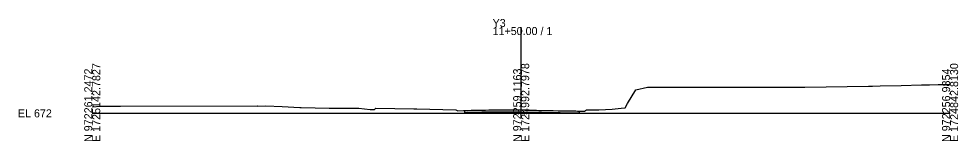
# Model space of a CAD drawing. Extents: x -26 to 303, y -10 to 3017.
# Drawn here: x -25.7 to 302.8, y 1490.3 to 1532.9 of the extents above; entities that cross this region are included whole.
import ezdxf

# ---------------------------------------------------------------- set-up
doc = ezdxf.new("R2010")
doc.units = 0
for name, color, linetype in [('Default', 7, 'Continuous'), ('Exist Other Culture Gate Leader', 7, 'Continuous'), ('Exist Roads Soil Text', 7, 'Continuous'), ('Exist Structure Minor Culvert Topo Terminator', 7, 'Continuous')]:
    doc.layers.add(name, color=color, linetype=linetype)

msp = doc.modelspace()

# ---------------------------------------------------------------- linework, layer by layer
at = {"layer": 'Exist Other Culture Gate Leader'}
for p, q in [((130.21, 1500.97), (130.21, 1500.3)), ((170.27, 1500.79), (170.27, 1500.12))]:
    msp.add_line(p, q, dxfattribs=at)
for points in [[(0, 1502.3), (2.84, 1502.51), (9.84, 1502.55), (57.83, 1502.66), (57.95, 1502.52), (60.76, 1502.64), (66.45, 1502.39), (72.54, 1502.08), (73.07, 1502.06), (82.84, 1501.83), (92.19, 1501.82), (93.19, 1501.81), (97.24, 1501.38), (97.81, 1501.36), (98.72, 1501.35), (99.14, 1501.85), (112.42, 1501.58), (112.85, 1501.57), (113.53, 1501.55), (127.17, 1501.27), (127.88, 1500.83), (129.8, 1500.94), (130.21, 1500.97), (131.22, 1501.04), (132.51, 1501.08), (133.72, 1501.11), (135.04, 1501.13), (136.22, 1501.14), (137.57, 1501.16), (138.7, 1501.17), (139.13, 1501.18), (139.68, 1501.19), (141.19, 1501.2), (142.28, 1501.21), (143.69, 1501.22), (145.15, 1501.22), (146.19, 1501.22), (147.2, 1501.21), (148.7, 1501.2), (149.42, 1501.19), (150, 1501.17), (151.23, 1501.13), (152.18, 1501.12), (153.73, 1501.1), (155.34, 1501.06), (156.23, 1501.04), (157.1, 1501.02), (158.73, 1500.98), (159.36, 1500.97), (159.88, 1500.96), (160.51, 1500.95), (161.21, 1500.94), (162.91, 1500.92), (163.7, 1500.91), (164.46, 1500.9), (166.19, 1500.87), (166.93, 1500.86), (168.69, 1500.83), (169.14, 1500.82), (169.72, 1500.81), (170.27, 1500.79), (171.8, 1500.74), (172.13, 1500.73), (172.85, 1501.2), (175.21, 1501.19), (177.16, 1501.2), (181.77, 1501.49), (184.98, 1501.75), (186.31, 1501.88), (187.21, 1503.39), (190.07, 1508.16), (194.2, 1509.13), (214.63, 1509.16), (222.7, 1509.11), (249.24, 1509.07), (271.43, 1509.46), (272.85, 1509.44), (275.5, 1509.57), (282.85, 1509.75), (290, 1509.91), (292.85, 1509.93), (295.79, 1510.01), (298.81, 1510.02), (300, 1510.03)], [(130.21, 1500.3), (131.25, 1500.38), (132.52, 1500.41), (133.73, 1500.44), (135.05, 1500.46), (136.23, 1500.48), (137.58, 1500.49), (138.71, 1500.5), (139.14, 1500.51), (139.69, 1500.52), (141.2, 1500.54), (142.28, 1500.55), (143.69, 1500.56), (145.15, 1500.55), (146.19, 1500.55), (147.19, 1500.54), (148.69, 1500.54), (149.4, 1500.52), (149.98, 1500.5), (151.22, 1500.46), (152.17, 1500.45), (153.72, 1500.43), (155.32, 1500.39), (156.22, 1500.37), (157.08, 1500.35), (158.71, 1500.31), (159.35, 1500.3), (159.87, 1500.29), (160.5, 1500.28), (161.2, 1500.28), (162.91, 1500.26), (163.69, 1500.25), (164.44, 1500.23), (166.18, 1500.2), (166.92, 1500.19), (168.68, 1500.16), (169.13, 1500.15), (169.7, 1500.14), (170.27, 1500.12)]]:
    msp.add_lwpolyline(points, dxfattribs=at)
at = {"layer": 'Exist Structure Minor Culvert Topo Terminator'}
for p, q in [((150, 1500), (150, 1530.08)), ((0, 1500), (150, 1500)), ((150, 1500), (300, 1500))]:
    msp.add_line(p, q, dxfattribs=at)

# ---------------------------------------------------------------- texts
at = {"layer": 'Default'}
msp.add_text('-', height=0.0001, dxfattribs=at).set_placement((0, 1500))
at = {"layer": 'Exist Roads Soil Text'}
msp.add_text('673.17', height=1, dxfattribs=at).set_placement((147.93, 1499.44))
at = {"layer": 'Exist Structure Minor Culvert Topo Terminator'}
for s, p in [('Y3', (140, 1530.08)), ('11+50.00 / 1', (140, 1527.28)), ('EL 672', (-26, 1498.6))]:
    msp.add_text(s, height=2.8, dxfattribs=at).set_placement(p)
for s, p in [('N 972261.2472', (0, 1490)), ('E 1725142.7827', (2.8, 1490)), ('N 972259.1163', (150, 1490)), ('E 1724992.7978', (152.8, 1490)), ('N 972256.9854', (300, 1490)), ('E 1724842.8130', (302.8, 1490))]:
    msp.add_text(s, height=2.8, rotation=90, dxfattribs=at).set_placement(p)

doc.saveas('drawing.dxf')
